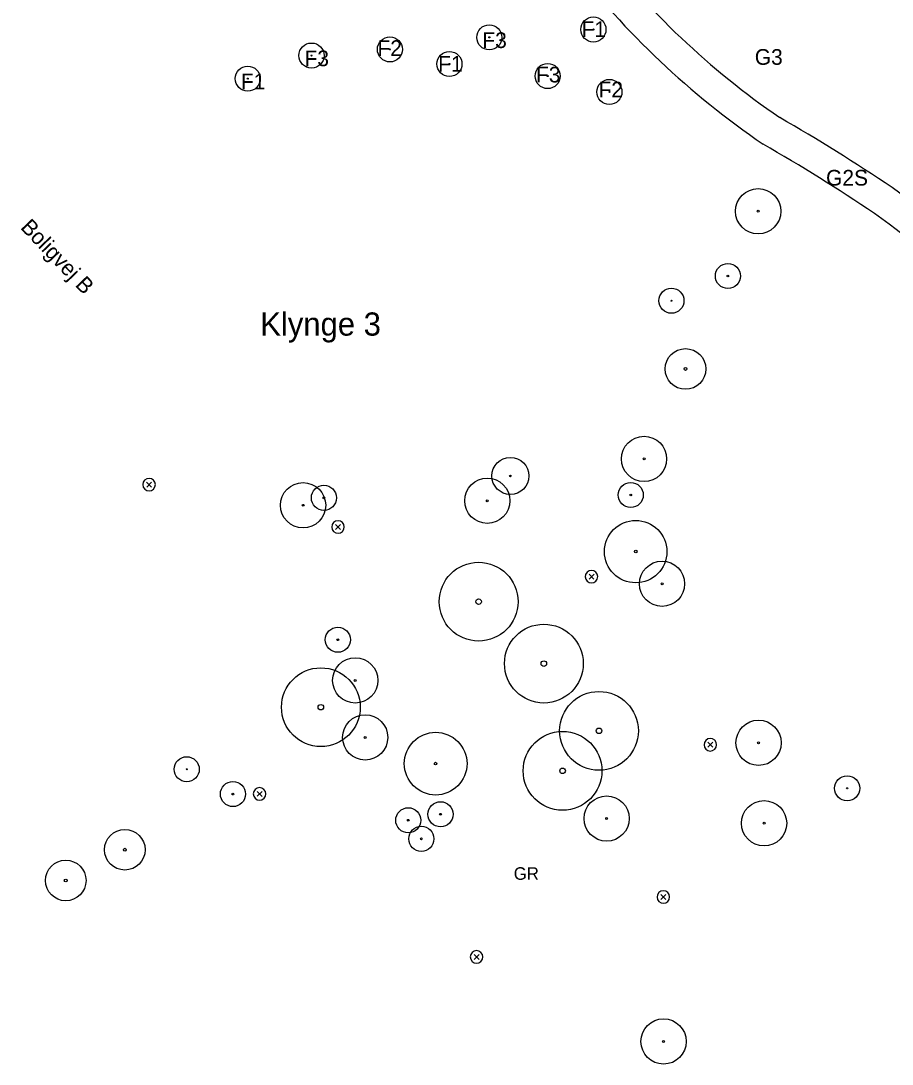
# Model space of a CAD drawing. Extents: x 0 to 512122, y 0 to 6212554.
# Drawn here: x 511595.4 to 511664.9, y 6211598.7 to 6211681.8 of the extents above; entities that cross this region are included whole.
import ezdxf

# ---------------------------------------------------------------- set-up
doc = ezdxf.new("R2010")
doc.units = 0
for name, color, linetype in [('_lights', 7, 'Continuous'), ('_ny fruit trees', 7, 'Continuous'), ('_ny text', 7, 'Continuous'), ('_Paths', 7, 'Continuous'), ('_solitaire tree_ K3', 7, 'Continuous'), ('TV_U_AFM_Symbl_Gul', 7, 'Continuous'), ('TV_U_LYS_Ledn-ror', 7, 'Continuous')]:
    doc.layers.add(name, color=color, linetype=linetype)

msp = doc.modelspace()

# ---------------------------------------------------------------- linework, layer by layer
at = {"layer": '_lights'}
for p, q in [((511605.471, 6211645.034), (511605.865, 6211644.64)), ((511605.869, 6211645.038), (511605.475, 6211644.644)), ((511620.537, 6211641.66), (511620.931, 6211641.266)), ((511620.935, 6211641.664), (511620.541, 6211641.27)), ((511640.747, 6211637.697), (511641.141, 6211637.303)), ((511641.145, 6211637.701), (511640.751, 6211637.307)), ((511650.22, 6211624.305), (511650.614, 6211623.911)), ((511650.618, 6211624.309), (511650.224, 6211623.915)), ((511614.281, 6211620.39), (511614.675, 6211619.996)), ((511614.679, 6211620.394), (511614.285, 6211619.999)), ((511646.48, 6211612.17), (511646.874, 6211611.775)), ((511646.878, 6211612.173), (511646.484, 6211611.779)), ((511631.581, 6211607.398), (511631.975, 6211607.004)), ((511631.979, 6211607.402), (511631.585, 6211607.008))]:
    msp.add_line(p, q, dxfattribs=at)
for centre, start, end in [((511605.668, 6211644.837), 315.56363, 315), ((511605.668, 6211644.837), 315, 315.56363), ((511620.734, 6211641.463), 315.56363, 315), ((511620.734, 6211641.463), 315, 315.56363), ((511640.944, 6211637.5), 315.56363, 315), ((511640.944, 6211637.5), 315, 315.56363), ((511650.417, 6211624.108), 315.56363, 315), ((511650.417, 6211624.108), 315, 315.56363), ((511614.478, 6211620.193), 315.56363, 315), ((511614.478, 6211620.193), 315, 315.56363), ((511646.677, 6211611.972), 315.56363, 315), ((511646.677, 6211611.972), 315, 315.56363), ((511631.778, 6211607.201), 315.56363, 315), ((511631.778, 6211607.201), 315, 315.56363)]:
    msp.add_arc(centre, 0.5, start, end, dxfattribs=at)
at = {"layer": '_ny fruit trees'}
for centre, radius in [((511641.096, 6211681.11), 1), ((511632.797, 6211680.481), 1), ((511641.096, 6211681.11), 0.0426), ((511618.615, 6211679.032), 1), ((511624.87, 6211679.52), 1), ((511632.797, 6211680.481), 0.0426), ((511624.87, 6211679.52), 0.0426), ((511629.618, 6211678.361), 1), ((511618.615, 6211679.032), 0.0426), ((511629.618, 6211678.361), 0.0426), ((511637.45, 6211677.397), 1), ((511613.535, 6211677.192), 1), ((511613.535, 6211677.192), 0.0426), ((511637.45, 6211677.397), 0.0426), ((511642.372, 6211676.132), 1), ((511642.372, 6211676.132), 0.0426), ((511654.235, 6211666.621), 1.806), ((511654.235, 6211666.621), 0.077), ((511647.321, 6211659.494), 1), ((511647.321, 6211659.494), 0.0426), ((511634.478, 6211645.53), 1.478), ((511634.478, 6211645.53), 0.063), ((511617.944, 6211643.19), 1.806), ((511617.944, 6211643.19), 0.077), ((511608.667, 6211622.156), 1), ((511608.667, 6211622.156), 0.0426), ((511661.335, 6211620.637), 1), ((511661.335, 6211620.637), 0.0426), ((511654.705, 6211617.853), 1.806), ((511654.705, 6211617.853), 0.077), ((511646.69, 6211600.463), 1.806), ((511646.69, 6211600.463), 0.077)]:
    msp.add_circle(centre, radius, dxfattribs=at)
at = {"layer": '_Paths'}
for centre, radius, start, end in [((511692.649, 6211727.61), 64.887, 217.68561, 235.56417), ((511692.649, 6211727.61), 67.387, 217.69879, 235.64829), ((511578.314, 6211539.414), 155.457, 56.14415, 60.03651), ((511578.314, 6211539.414), 152.957, 56.15274, 60.07258), ((511637.775, 6211629.597), 47.447, 25.82266, 55.10263), ((511637.775, 6211629.597), 44.947, 25.82266, 55.07394)]:
    msp.add_arc(centre, radius, start, end, dxfattribs=at)
at = {"layer": '_solitaire tree_ K3'}
for centre, radius in [((511651.821, 6211661.463), 1), ((511651.821, 6211661.463), 0.0703), ((511648.443, 6211654.057), 1.622), ((511648.443, 6211654.057), 0.114), ((511645.136, 6211646.884), 1.803), ((511645.136, 6211646.884), 0.0768), ((511632.637, 6211643.555), 1.803), ((511619.608, 6211643.786), 1), ((511644.077, 6211644.012), 1), ((511619.608, 6211643.786), 0.0703), ((511632.637, 6211643.555), 0.0768), ((511644.077, 6211644.012), 0.0703), ((511644.468, 6211639.502), 2.487), ((511644.468, 6211639.502), 0.106), ((511631.944, 6211635.511), 3.14), ((511646.571, 6211636.934), 1.803), ((511646.571, 6211636.934), 0.0768), ((511631.944, 6211635.511), 0.221), ((511620.719, 6211632.476), 1), ((511637.146, 6211630.575), 3.14), ((511620.719, 6211632.476), 0.0703), ((511622.107, 6211629.236), 1.803), ((511619.365, 6211627.099), 3.14), ((511637.146, 6211630.575), 0.221), ((511622.107, 6211629.236), 0.0768), ((511641.542, 6211625.214), 3.14), ((511619.365, 6211627.099), 0.221), ((511622.897, 6211624.695), 1.803), ((511654.265, 6211624.262), 1.803), ((511638.638, 6211622.031), 3.14), ((511641.542, 6211625.214), 0.221), ((511622.897, 6211624.695), 0.0768), ((511628.518, 6211622.602), 2.499), ((511654.265, 6211624.262), 0.0768), ((511628.518, 6211622.602), 0.106), ((511638.638, 6211622.031), 0.221), ((511612.353, 6211620.179), 1), ((511612.353, 6211620.179), 0.0703), ((511628.906, 6211618.567), 1), ((511642.153, 6211618.229), 1.803), ((511626.332, 6211618.09), 1), ((511628.906, 6211618.567), 0.0703), ((511626.332, 6211618.09), 0.0703), ((511642.153, 6211618.229), 0.0768), ((511603.73, 6211615.742), 1.619), ((511627.376, 6211616.611), 1), ((511627.376, 6211616.611), 0.0703), ((511603.73, 6211615.742), 0.114), ((511599.019, 6211613.294), 1.619), ((511599.019, 6211613.294), 0.114)]:
    msp.add_circle(centre, radius, dxfattribs=at)

# ---------------------------------------------------------------- texts
at = {"layer": '_ny text'}
msp.add_text('GR', height=1, dxfattribs=at).set_placement((511634.744, 6211613.347))
at = {"layer": 'TV_U_AFM_Symbl_Gul'}
for s, p in [('F1', (511640.148, 6211680.509)), ('F3', (511632.243, 6211679.632)), ('F2', (511623.876, 6211678.999)), ('F3', (511618.061, 6211678.184)), ('G3', (511653.965, 6211678.295)), ('F1', (511628.717, 6211677.748)), ('F1', (511612.981, 6211676.344)), ('F3', (511636.523, 6211676.889)), ('F2', (511641.505, 6211675.697)), ('G2S', (511659.651, 6211668.669))]:
    msp.add_text(s, height=1.25, dxfattribs=at).set_placement(p)
msp.add_text('Boligvej B', height=1.25, rotation=313.73963, dxfattribs=at).set_placement((511595.345, 6211665.279))
at = {"layer": 'TV_U_LYS_Ledn-ror'}
msp.add_text('Klynge 3', height=1.8481, dxfattribs=at).set_placement((511614.533, 6211656.711))

doc.saveas('drawing.dxf')
